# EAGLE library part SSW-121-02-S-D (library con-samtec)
THROUGH-HOLE .025" SQ POST SOCKET Source: Samtec SSW.pdf
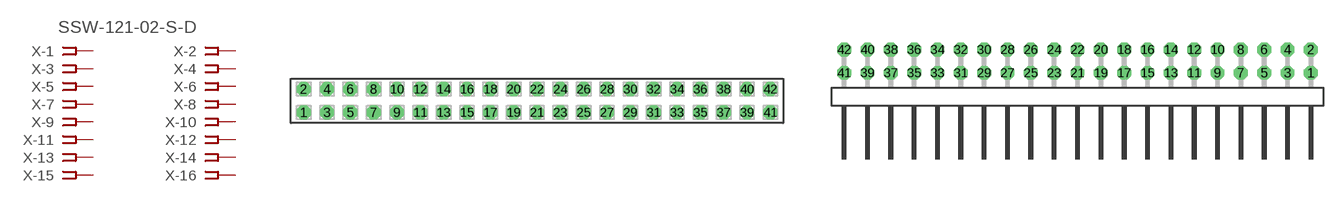
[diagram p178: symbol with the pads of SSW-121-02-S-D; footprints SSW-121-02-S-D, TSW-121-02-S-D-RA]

Designator prefix X; gates -1=FPINV -2=FPIN -3=FPIN -4=FPIN -5=FPIN -6=FPIN -7=FPIN -8=FPIN -9=FPIN -10=FPIN -11=FPIN -12=FPIN -13=FPIN -14=FPIN -15=FPIN -16=FPIN -17=FPIN -18=FPIN -19=FPIN -20=FPIN -21=FPIN -22=FPIN -23=FPIN -24=FPIN -25=FPIN -26=FPIN -27=FPIN -28=FPIN -29=FPIN -30=FPIN -31=FPIN -32=FPIN -33=FPIN -34=FPIN -35=FPIN -36=FPIN -37=FPIN -38=FPIN -39=FPIN -40=FPIN -41=FPIN -42=FPIN

## SSW-121-02-S-D (MPN: SSW-121-02-S-D; OC_FARNELL: unknown; OC_NEWARK: 11P9656)  [SSW-121-02-S-D]
1  -1:1  pas
2  -2:1  pas
3  -3:1  pas
4  -4:1  pas
5  -5:1  pas
6  -6:1  pas
7  -7:1  pas
8  -8:1  pas
9  -9:1  pas
10  -10:1  pas
11  -11:1  pas
12  -12:1  pas
13  -13:1  pas
14  -14:1  pas
15  -15:1  pas
16  -16:1  pas
17  -17:1  pas
18  -18:1  pas
19  -19:1  pas
20  -20:1  pas
21  -21:1  pas
22  -22:1  pas
23  -23:1  pas
24  -24:1  pas
25  -25:1  pas
26  -26:1  pas
27  -27:1  pas
28  -28:1  pas
29  -29:1  pas
30  -30:1  pas
31  -31:1  pas
32  -32:1  pas
33  -33:1  pas
34  -34:1  pas
35  -35:1  pas
36  -36:1  pas
37  -37:1  pas
38  -38:1  pas
39  -39:1  pas
40  -40:1  pas
41  -41:1  pas
42  -42:1  pas

## SSW-121-02-S-D-RA (MPN: SSW-121-02-S-D-RA; OC_FARNELL: unknown; OC_NEWARK: 11P9657)  [TSW-121-02-S-D-RA]
Pads as for SSW-121-02-S-D

## Footprint SSW-121-02-S-D (pad centres in mm)
THROUGH-HOLE .025" SQ POST SOCKET Source: Samtec SSW.pdf
drill 1 pad 1.5 octagon: 1 -25.4,-1.27; 2 -25.4,1.27; 3 -22.86,-1.27; 4 -22.86,1.27; 5 -20.32,-1.27; 6 -20.32,1.27; 7 -17.78,-1.27; 8 -17.78,1.27; 9 -15.24,-1.27; 10 -15.24,1.27; 11 -12.7,-1.27; 12 -12.7,1.27; 13 -10.16,-1.27; 14 -10.16,1.27; 15 -7.62,-1.27; 16 -7.62,1.27; 17 -5.08,-1.27; 18 -5.08,1.27; 19 -2.54,-1.27; 20 -2.54,1.27; 21 0,-1.27; 22 0,1.27; 23 2.54,-1.27; 24 2.54,1.27; 25 5.08,-1.27; 26 5.08,1.27; 27 7.62,-1.27; 28 7.62,1.27; 29 10.16,-1.27; 30 10.16,1.27; 31 12.7,-1.27; 32 12.7,1.27; 33 15.24,-1.27; 34 15.24,1.27; 35 17.78,-1.27; 36 17.78,1.27; 37 20.32,-1.27; 38 20.32,1.27; 39 22.86,-1.27; 40 22.86,1.27; 41 25.4,-1.27; 42 25.4,1.27

## Footprint TSW-121-02-S-D-RA (pad centres in mm)
THROUGH-HOLE .025" SQ POST HEADER Source: Samtec TSW.pdf
drill 1 pad 1.5 octagon: 1 25.4,1.524; 2 25.4,4.064; 3 22.86,1.524; 4 22.86,4.064; 5 20.32,1.524; 6 20.32,4.064; 7 17.78,1.524; 8 17.78,4.064; 9 15.24,1.524; 10 15.24,4.064; 11 12.7,1.524; 12 12.7,4.064; 13 10.16,1.524; 14 10.16,4.064; 15 7.62,1.524; 16 7.62,4.064; 17 5.08,1.524; 18 5.08,4.064; 19 2.54,1.524; 20 2.54,4.064; 21 0,1.524; 22 0,4.064; 23 -2.54,1.524; 24 -2.54,4.064; 25 -5.08,1.524; 26 -5.08,4.064; 27 -7.62,1.524; 28 -7.62,4.064; 29 -10.16,1.524; 30 -10.16,4.064; 31 -12.7,1.524; 32 -12.7,4.064; 33 -15.24,1.524; 34 -15.24,4.064; 35 -17.78,1.524; 36 -17.78,4.064; 37 -20.32,1.524; 38 -20.32,4.064; 39 -22.86,1.524; 40 -22.86,4.064; 41 -25.4,1.524; 42 -25.4,4.064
